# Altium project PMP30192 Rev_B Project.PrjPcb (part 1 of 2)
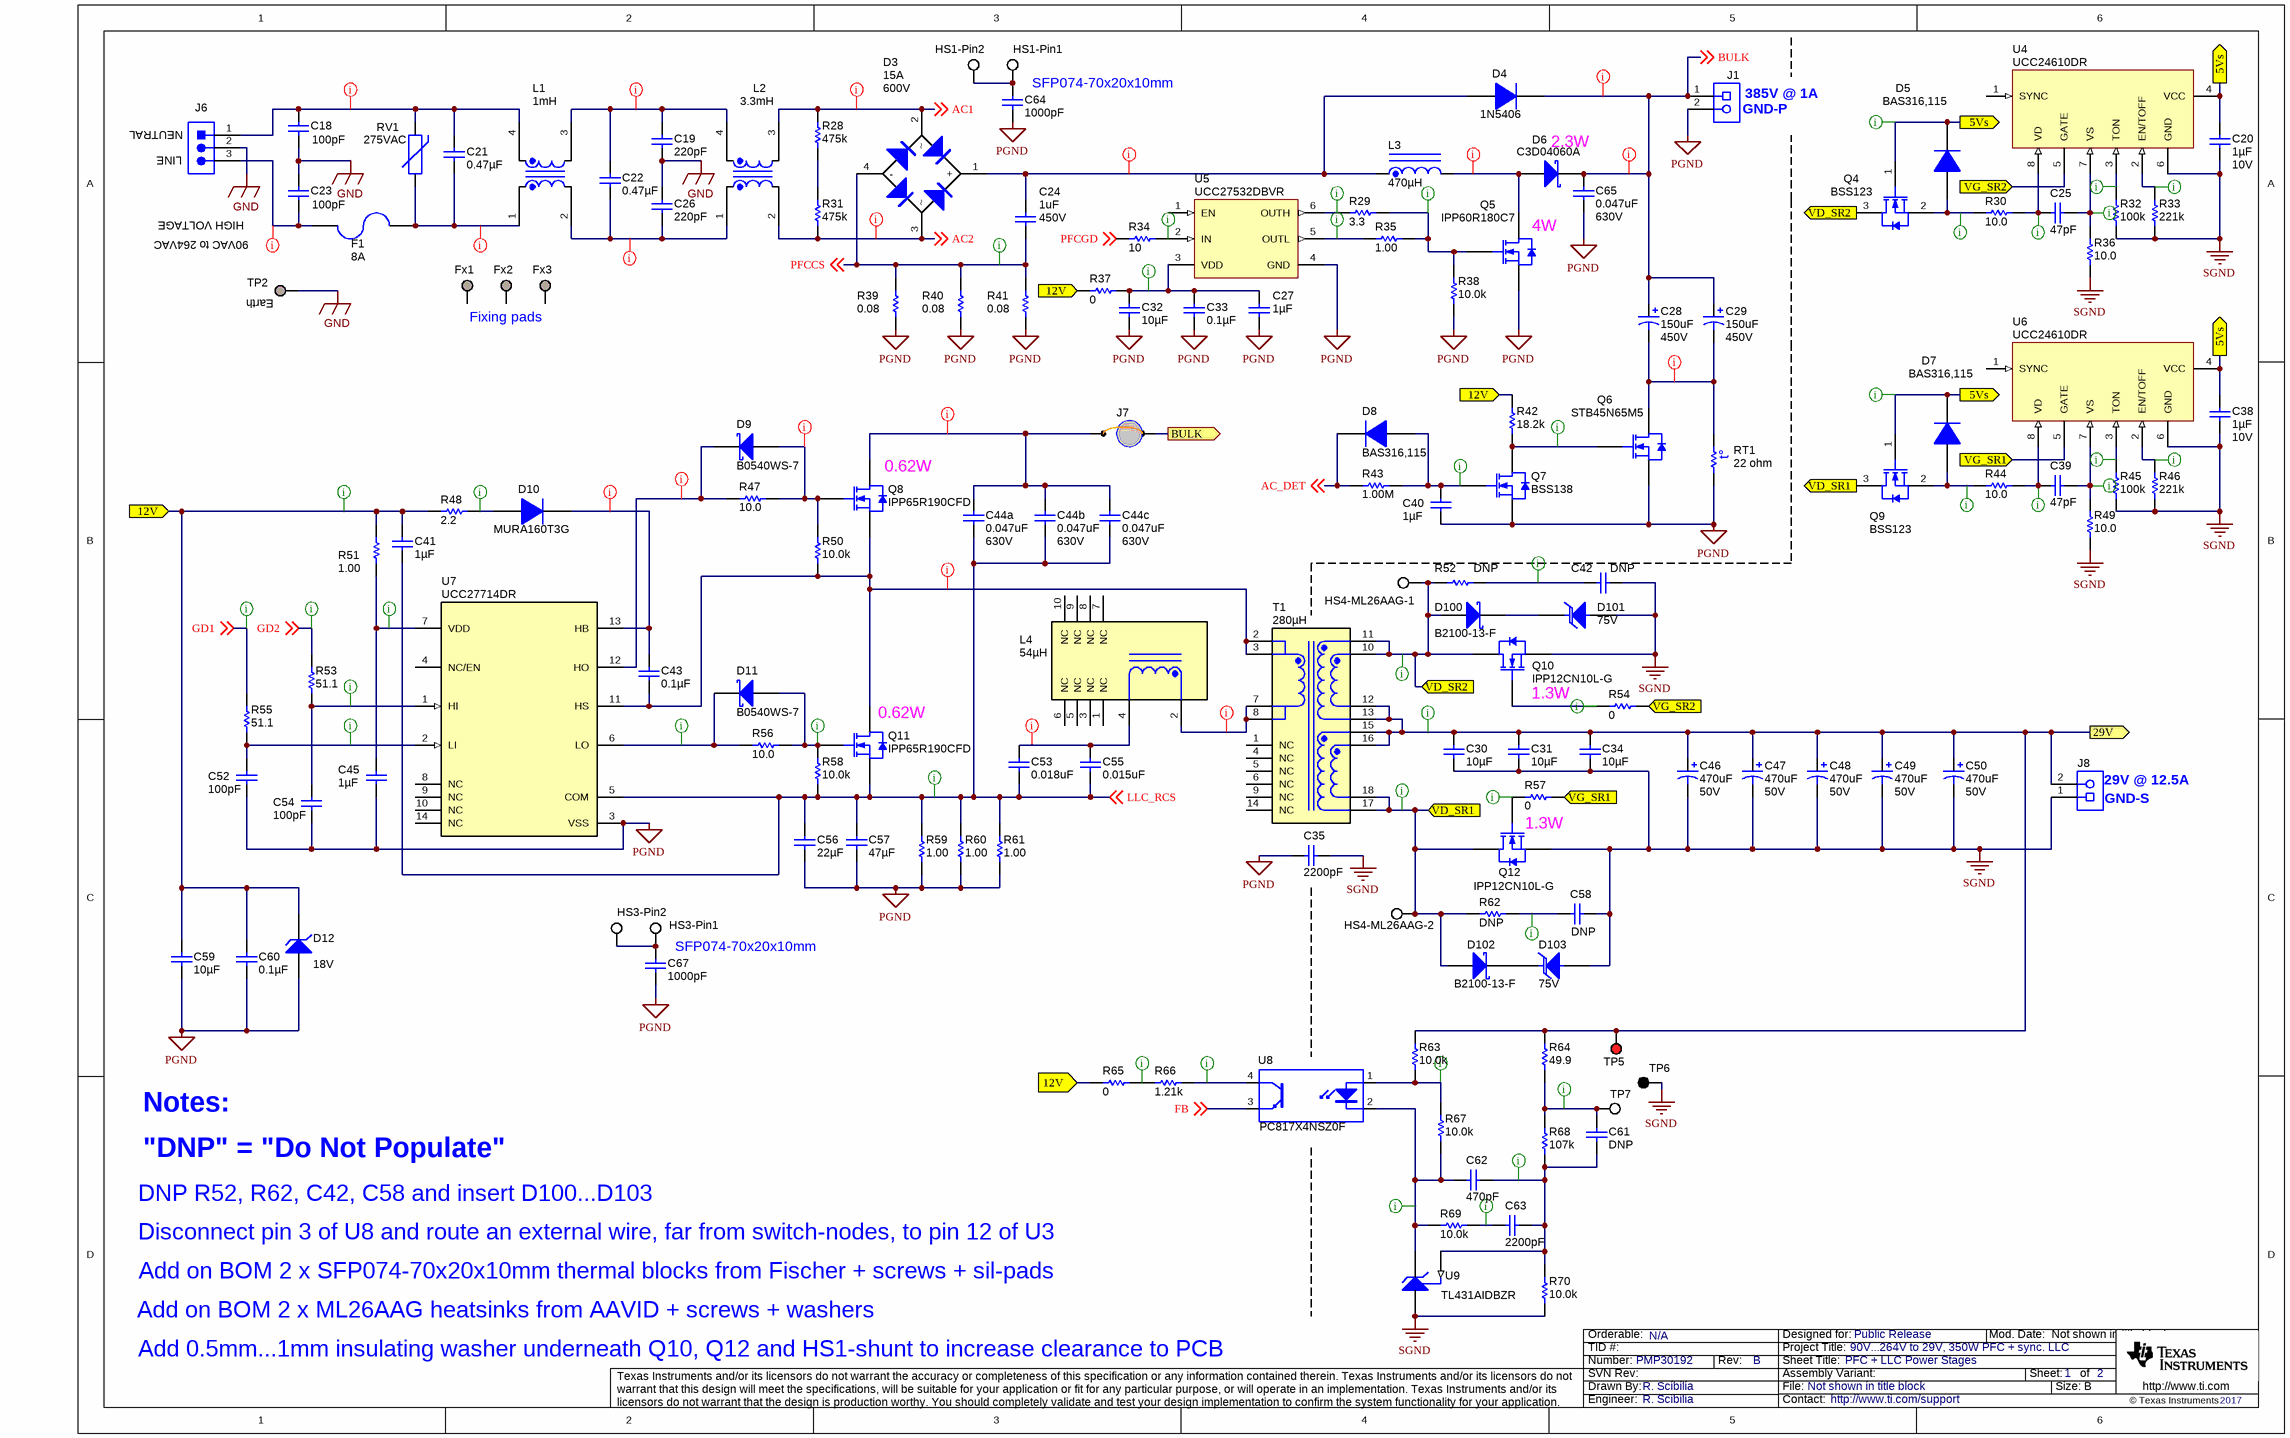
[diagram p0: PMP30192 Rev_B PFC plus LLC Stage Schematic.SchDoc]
CopyrightYear: 2017; EVM_Orderable: N/A; PCB_Layout: R. Scibilia; PCB_Rev: A; PRJ_Customer: Public Release; PRJ_Engineer: R. Scibilia; PRJ_Number: PMP30192; PRJ_Title: 90V...264V to 29V, 350W PFC + sync. LLC; SCH_Rev: B; TechSupport: http://www.ti.com/support
2 sheets, 202 parts. Net scope: flat (ports and power ports of the same name join across sheets).
Board file: PMP30192 Rev_A PCB.PcbDoc
Sheets:
  PMP30192 Rev_B PFC plus LLC Stage Schematic.SchDoc
  PMP30192 Rev_B Modulator Schematic.SchDoc

## Sheet PMP30192 Rev_B PFC plus LLC Stage Schematic.SchDoc: PFC + LLC Power Stages
size 431 x 279 mm; Date: Not shown in title block; ApprovedBy: Not shown in title block; CheckedBy: Not shown in title block; Author: Not shown in title block; CompanyName: Not shown in title block; DrawnBy: R. Scibilia; Engineer: Not shown in title block; Organization: Not shown in title block; Address1: Not shown in title block; Address2: Not shown in title block; Address3: Not shown in title block; Address4: Not shown in title block; DocumentNumber: 1; Revision: Use project parameter SCH_Rev; SheetNumber: 1; SheetTotal: 2; PageSetup: Record=PageOptions¦CenterHorizontal=True¦CenterVertical=True¦PrintScale=1.00¦XCorrection=1.00¦YCorrection=1.00¦PrintKind=0¦BorderSize=5000000¦LeftOffset=0¦BottomOffset=0¦Orientation=2¦PaperLength=1000¦PaperWidth=1000¦Scale=100¦PaperSource=15¦PrintQuality=600¦MediaType=1¦DitherType=10¦PaperKind=Letter¦PrintScaleMode=1

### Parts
C18  Value1: 100pF  [B_800x700x800]  (hidden comment: DE6B3KJ101KN3A)
C19  ValueDisplayed: 220pF  [B_800x700x800]  (hidden comment: DE6B3KJ221KN3A)
C20  ValueDisplayed: 1µF  Value2: 10V  [0603]  (hidden comment: C0603C105K8PACTU)
C21  ValueDisplayed: 0.47µF  [CAPRR2250W80L2550T850H1750]  (hidden comment: ECQ-U2A474ML)
C22  ValueDisplayed: 0.47µF  [CAPRR2250W80L2550T850H1750]  (hidden comment: ECQ-U2A474ML)
C23  Value1: 100pF  [B_800x700x800]  (hidden comment: DE6B3KJ101KN3A)
C24  value 1uF  Value2: 450V  [B32672_1800x1100x1850]  (hidden comment: B32672Z4105K000)
C25  ValueDisplayed: 47pF  [0603]  (hidden comment: C0603C470J5GACTU)
C26  ValueDisplayed: 220pF  [B_800x700x800]  (hidden comment: DE6B3KJ221KN3A)
C27  ValueDisplayed: 1µF  [0603]  (hidden comment: UMK107AB7105KA-T)
C28  value 150uF  Value2: 450V  [KXW_1800x4500]  (hidden comment: 450TXW150MEFC18X45)
C29  value 150uF  Value2: 450V  [KXW_1800x4500]  (hidden comment: 450TXW150MEFC18X45)
C30  ValueDisplayed: 10µF  [1206_180]  (hidden comment: C3216X5R1H106K160AB)
C31  ValueDisplayed: 10µF  [1206_180]  (hidden comment: C3216X5R1H106K160AB)
C32  ValueDisplayed: 10µF  [1206]  (hidden comment: GMK316AB7106KL)
C33  ValueDisplayed: 0.1µF  [0603]  (hidden comment: 06035C104KAT2A)
C34  ValueDisplayed: 10µF  [1206_180]  (hidden comment: C3216X5R1H106K160AB)
C35  ValueDisplayed: 2200pF  [E_900x700x900]  (hidden comment: DE6E3KJ222MN3A)
C38  ValueDisplayed: 1µF  Value2: 10V  [0603]  (hidden comment: C0603C105K8PACTU)
C39  ValueDisplayed: 47pF  [0603]  (hidden comment: C0603C470J5GACTU)
C40  ValueDisplayed: 1µF  [0603]  (hidden comment: UMK107AB7105KA-T)
C41  ValueDisplayed: 1µF  [0603]  (hidden comment: UMK107AB7105KA-T)
C42  value DNP  [1206]  (hidden comment: Used in BOM report)
C43  ValueDisplayed: 0.1µF  [0603]  (hidden comment: 06035C104KAT2A)
C44a  value 0.047uF  Value2: 630V  [1210_220]  (hidden comment: GRM32DR72J473KW01L)
C44b  value 0.047uF  Value2: 630V  [1210_220]  (hidden comment: GRM32DR72J473KW01L)
C44c  value 0.047uF  Value2: 630V  [1210_220]  (hidden comment: GRM32DR72J473KW01L)
C45  ValueDisplayed: 1µF  [0603]  (hidden comment: UMK107AB7105KA-T)
C46  value 470uF  Value2: 50V  [ZLH_1250x2500]  (hidden comment: 50ZLH470M12.5X20)
C47  value 470uF  Value2: 50V  [ZLH_1250x2500]  (hidden comment: 50ZLH470M12.5X20)
C48  value 470uF  Value2: 50V  [ZLH_1250x2500]  (hidden comment: 50ZLH470M12.5X20)
C49  value 470uF  Value2: 50V  [ZLH_1250x2500]  (hidden comment: 50ZLH470M12.5X20)
C50  value 470uF  Value2: 50V  [ZLH_1250x2500]  (hidden comment: 50ZLH470M12.5X20)
C52  ValueDisplayed: 100pF  [0603]  (hidden comment: 06035A101FAT2A)
C53  value 0.018uF  [CAPRR1500W80L1800T800H1550]  (hidden comment: 121MPE183J)
C54  ValueDisplayed: 100pF  [0603]  (hidden comment: 06035A101FAT2A)
C55  value 0.015uF  [CAPRR1500W80L1800T800H1550]  (hidden comment: 121MPE153J)
C56  ValueDisplayed: 22µF  [1206_180]  (hidden comment: C3216X6S1A226M160AB)
C57  ValueDisplayed: 47µF  [1206]  (hidden comment: C3216X5R1C476M160AB)
C58  value DNP  [1206]  (hidden comment: Used in BOM report)
C59  ValueDisplayed: 10µF  [1206]  (hidden comment: GMK316AB7106KL)
C60  ValueDisplayed: 0.1µF  [0603]  (hidden comment: 06035C104KAT2A)
C61  DNP  [0603]
C62  ValueDisplayed: 470pF  [0603]  (hidden comment: GCM1885C1H471JA16D)
C63  ValueDisplayed: 2200pF  [0603]  (hidden comment: C0603C222K5RACTU)
C64  ValueDisplayed: 1000pF  [1206]  (hidden comment: GRM31BR72J102KW01L)
C65  value 0.047uF  Value2: 630V  [1210_220]  (hidden comment: GRM32DR72J473KW01L)
C67  ValueDisplayed: 1000pF  [1206]  (hidden comment: GRM31BR72J102KW01L)
D3  value 600V  Value1: 15A  [GBJ]  (hidden comment: GBJL2006-BP)
D4  1N5406  [DO-201AD]
D5  BAS316,115  [sod-323]
D6  C3D04060A  [TO-220-F2]
D7  BAS316,115  [sod-323]
D8  BAS316,115  [sod-323]
D9  B0540WS-7  [SOD-323]
D10  MURA160T3G  [SMA]
D11  B0540WS-7  [SOD-323]
D12  value 18V  [SOD-123]  (hidden comment: MMSZ5248B-7-F)
D100  B2100-13-F  [SMB]
D101  value 75V  [SMB]  (hidden comment: SMBJ75A-13-F)
D102  B2100-13-F  [SMB]
D103  value 75V  [SMB]  (hidden comment: SMBJ75A-13-F)
F1  value 8A  [FUSE_0216]  (hidden comment: 0216008.MXESPP)
Fx1  TESTPOINT  [PAD_100mil-40milhole]  (value not drawn)  (no BOM)
Fx2  TESTPOINT  [PAD_100mil-40milhole]  (value not drawn)  (no BOM)
Fx3  TESTPOINT  [PAD_100mil-40milhole]  (value not drawn)  (no BOM)
HS1-Pin1  5012  [Keystone5012]  (value not drawn)
HS1-Pin2  5012  [Keystone5012]  (value not drawn)
HS3-Pin1  5012  [Keystone5012]  (value not drawn)
HS3-Pin2  5012  [Keystone5012]  (value not drawn)
HS4-ML26AAG-1  5012  [Keystone5012]  (value not drawn)
HS4-ML26AAG-2  5012  [Keystone5012]  (value not drawn)
J1  1715721  [PhoenixContact_1715721]  (value not drawn)
J6  1-1318301-3  [TE_1-1318301-3]  (value not drawn)
J7  923345-03-C  [923345-03-C]  (value not drawn)
J8  1732720  [Phoenix_1732720]  (value not drawn)
L1  value 1mH  [WE-CMBH]  (hidden comment: 744834101)
L2  value 3.3mH  [WE-CMBH]  (hidden comment: 744834433)
L3  ValueDisplayed: 470µH  [750316597]  (hidden comment: 750316597)
L4  ValueDisplayed: 54µH  [750316600]  (hidden comment: 750316600)
Q4  BSS123  [SOT-23]
Q5  IPP60R180C7  [TO-220AB]
Q6  STB45N65M5  [DDPAK]
Q7  BSS138  [SOT-23]
Q8  IPP65R190CFD  [TO-220AB]
Q9  BSS123  [SOT-23]
Q10  value IPP12CN10L-G  [TO-220AB]  (hidden comment: IPP12CN10L G)
Q11  IPP65R190CFD  [TO-220AB]
Q12  value IPP12CN10L-G  [TO-220AB]  (hidden comment: IPP12CN10L G)
R28  ValueDisplayed: 475k  [1206]  (hidden comment: ERJ-8ENF4753V)
R29  ValueDisplayed: 3.3  [0603]  (hidden comment: CRCW06033R30JNEA)
R30  ValueDisplayed: 10.0  [0603]  (hidden comment: RC0603FR-0710RL)
R31  ValueDisplayed: 475k  [1206]  (hidden comment: ERJ-8ENF4753V)
R32  value 100k  [0603]  (hidden comment: CRCW0603100KFKEA)
R33  value 221k  [0603]  (hidden comment: CRCW0603221KFKEA)
R34  ValueDisplayed: 10  [0603]  (hidden comment: CRCW060310R0JNEA)
R35  ValueDisplayed: 1.00  [0603]  (hidden comment: CRCW06031R00FKEA)
R36  ValueDisplayed: 10.0  [0603]  (hidden comment: RC0603FR-0710RL)
R37  ValueDisplayed: 0  [1206]  (hidden comment: CRCW12060000Z0EA)
R38  value 10.0k  [0603]  (hidden comment: CRCW060310K0FKEA)
R39  ValueDisplayed: 0.08  [2512]  (hidden comment: CRA2512-FZ-R080ELF)
R40  ValueDisplayed: 0.08  [2512]  (hidden comment: CRA2512-FZ-R080ELF)
R41  ValueDisplayed: 0.08  [2512]  (hidden comment: CRA2512-FZ-R080ELF)
R42  ValueDisplayed: 18.2k  [0603]  (hidden comment: RC0603FR-0718K2L)
R43  ValueDisplayed: 1.00M  [0603]  (hidden comment: RC0603FR-071ML)
R44  ValueDisplayed: 10.0  [0603]  (hidden comment: RC0603FR-0710RL)
R45  value 100k  [0603]  (hidden comment: CRCW0603100KFKEA)
R46  value 221k  [0603]  (hidden comment: CRCW0603221KFKEA)
R47  ValueDisplayed: 10.0  [1206]  (hidden comment: RC1206FR-0710RL)
R48  ValueDisplayed: 2.2  [0805_HV]  (hidden comment: CRCW08052R20JNEA)
R49  ValueDisplayed: 10.0  [0603]  (hidden comment: RC0603FR-0710RL)
R50  value 10.0k  [0603]  (hidden comment: CRCW060310K0FKEA)
R51  value 1.00  [0805_HV]  (hidden comment: ERJ-6RQF1R0V)
R52  ERJ-1TYJ100U  [2512]  (value not drawn)
R53  ValueDisplayed: 51.1  [0603]  (hidden comment: CRCW060351R1FKEA)
R54  ValueDisplayed: 0  [0603]  (hidden comment: CRCW06030000Z0EA)
R55  ValueDisplayed: 51.1  [0603]  (hidden comment: CRCW060351R1FKEA)
R56  ValueDisplayed: 10.0  [1206]  (hidden comment: RC1206FR-0710RL)
R57  ValueDisplayed: 0  [0603]  (hidden comment: CRCW06030000Z0EA)
R58  value 10.0k  [0603]  (hidden comment: CRCW060310K0FKEA)
R59  ValueDisplayed: 1.00  [2512]  (hidden comment: ERJ-1TRQF1R0U)
R60  ValueDisplayed: 1.00  [2512]  (hidden comment: ERJ-1TRQF1R0U)
R61  ValueDisplayed: 1.00  [2512]  (hidden comment: ERJ-1TRQF1R0U)
R62  ERJ-1TYJ100U  [2512]  (value not drawn)
R63  value 10.0k  [0603]  (hidden comment: CRCW060310K0FKEA)
R64  ValueDisplayed: 49.9  [0603]  (hidden comment: RC0603FR-0749R9L)
R65  ValueDisplayed: 0  [0603]  (hidden comment: CRCW06030000Z0EA)
R66  ValueDisplayed: 1.21k  [0603]  (hidden comment: RC0603FR-071K21L)
R67  value 10.0k  [0603]  (hidden comment: CRCW060310K0FKEA)
R68  ValueDisplayed: 107k  [0603]  (hidden comment: RC0603FR-07107KL)
R69  value 10.0k  [0603]  (hidden comment: CRCW060310K0FKEA)
R70  value 10.0k  [0603]  (hidden comment: CRCW060310K0FKEA)
RT1  value 22 ohm  [S237]  (hidden comment: B57237S220M)
RV1  value 275VAC  [VAR_B72214S0271]  (hidden comment: B72214S0271K101)
T1  ValueDisplayed: 280µH  [Wurth_750316599]  (hidden comment: 750316599)
TP2  TESTPOINT  [PAD_100mil-40milhole]  (value not drawn)  (no BOM)
TP5  5010  [Keystone5010]  (value not drawn)
TP6  5011  [Keystone5011]  (value not drawn)
TP7  5012  [Keystone5012]  (value not drawn)
U4  UCC24610DR  [D0008A_N]
U5  UCC27532DBVR  [DBV0006A_N]
U6  UCC24610DR  [D0008A_N]
U7  UCC27714DR  [D0014A_N]
U8  PC817X4NSZ0F  [DIP762W60P254L460H350Q4B]
U9  TL431AIDBZR  [DBZ0003A_N]

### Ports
5Vs, 12V, 29V, BULK, VD_SR1, VD_SR2, VG_SR1, VG_SR2

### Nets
GND: C18.2 C19.2 C23.1 C26.1 J6.2 TP2.1
PGND: C27.1 C32.1 C33.2 C35.2 C40.1 C45.1 C52.2 C54.1 C56.2 C57.2 C59.1 C60.2 C64.2 C65.1 C67.2 D12.2(A) J1.2 Q5.3(S) Q6.3(S) Q7.2(S) R38.2 R39.1 R40.1 R41.1 R59.1 R60.1 R61.1 RT1.1 U5.4(GND) U7.3(VSS)
SGND: C20.2 C30.2 C31.2 C34.2 C35.1 C38.2 C42.1 C46.2(-) C47.2(-) C48.2(-) C49.2(-) C50.2(-) C58.1 D101.2(A) D103.2(A) J8.1 Q10.3(S) Q12.3(S) R32.1 R33.1 R36.2 R45.1 R46.1 R49.2 R70.1 TP6.1 U4.6(GND) U6.6(GND) U9.3(ANODE)
5Vs: C20.1 C38.1 D5.1(K) D7.1(K) Q4.1(G) Q9.1(G) U4.4(VCC) U6.4(VCC) ; port 5Vs
12V: C41.2 C59.2 C60.1 D12.1(K) R37.1 R42.2 R48.1 R51.2 R65.1 ; port 12V
29V: C30.1 C31.1 C34.1 C46.1(+) C47.1(+) C48.1(+) C49.1(+) C50.1(+) J8.2 R63.2 R64.2 T1.12 T1.13 T1.15 T1.16 TP5.1 ; port 29V
AC1: D3.2 L2.3 R28.2 ; off-sheet AC1
AC2: D3.3 L2.2 R31.1 ; off-sheet AC2
AC_DET: D8.1(K) R43.1 ; off-sheet AC_DET
BULK: C28.1(+) C29.1(+) C65.2 D4.1(K) D6.1(K) J1.1 ; off-sheet BULK
BULK: J7.2 ; port BULK  [a separate net that carries the same name]
FB: U8.3(E) ; off-sheet FB
GD1: R55.2 ; off-sheet GD1
GD2: R53.2 ; off-sheet GD2
LLC_RCS: C41.1 C44a.1 C44b.1 C44c.1 C53.2 C55.2 C56.1 C57.1 Q11.3(S) R58.2 R59.2 R60.2 R61.2 U7.5(COM) ; off-sheet LLC_RCS
PFCCS: C24.2 D3.4(-) R39.2 R40.2 R41.2 ; off-sheet PFCCS
PFCGD: R34.2 ; off-sheet PFCGD
VD_SR1: D102.2(A) HS4-ML26AAG-2.1 Q9.3(D) Q12.2(D) R62.1 T1.17 T1.18 ; port VD_SR1
VD_SR2: D100.2(A) HS4-ML26AAG-1.1 Q4.3(D) Q10.2(D) R52.1 T1.10 T1.11 ; port VD_SR2
VG_SR1: R57.2 U6.5(GATE) ; port VG_SR1
VG_SR2: R54.2 U4.5(GATE) ; port VG_SR2
NetC18_1: C18.1 C21.1 J6.1 L1.4 RV1.2
NetC19_1: C19.1 C22.1 L1.3 L2.4
NetC21_2: C21.2 F1.1 L1.1 RV1.1
NetC22_2: C22.2 C26.2 L1.2 L2.1
NetC23_2: C23.2 F1.2 J6.3
NetC24_1: C24.1 D3.1(+) D4.2(A) L3.1
NetC25_1: C25.1 R36.1 U4.7(VS)
NetC25_2: C25.2 R30.2 U4.8(VD)
NetC27_2: C27.2 C32.2 C33.1 R37.2 U5.3(VDD)
NetC28_2: C28.2(-) C29.2(-) Q6.4(D) RT1.2
NetC39_1: C39.1 R49.1 U6.7(VS)
NetC39_2: C39.2 R44.2 U6.8(VD)
NetC40_2: C40.2 D8.2(A) Q7.1(G) R43.2
NetC42_2: C42.2 R52.2
NetC43_1: C43.1 D10.1(K) U7.13(HB)
NetC43_2: C43.2 Q8.3(S) Q11.2(D) R50.1 T1.2 T1.3 U7.11(HS)
NetC44a_2: C44a.2 C44b.2 C44c.2 J7.1 Q8.2(D)
NetC45_2: C45.2 R51.1 U7.7(VDD)
NetC52_1: C52.1 R55.1 U7.2(LI)
NetC53_1: C53.1 C55.1 L4.4
NetC54_2: C54.2 R53.1 U7.1(HI)
NetC58_2: C58.2 R62.2
NetC61_1: C61.1 R64.1 R68.2 TP7.1
NetC61_2: C61.2 C62.2 C63.2 R68.1 R70.2 U9.2(REF)
NetC62_1: C62.1 R67.1 R69.1 U8.2(K) U9.1(CATHODE)
NetC63_1: C63.1 R69.2
NetC64_1: C64.1 HS1-Pin1.1 HS1-Pin2.1
NetC67_1: C67.1 HS3-Pin1.1 HS3-Pin2.1
NetD5_2: D5.2(A) Q4.2(S) R30.1
NetD6_2: D6.2(A) L3.2 Q5.2(D)
NetD7_2: D7.2(A) Q9.2(S) R44.1
NetD9_1: D9.1(K) R47.1 U7.12(HO)
NetD9_2: D9.2(A) Q8.1(G) R47.2 R50.2
NetD10_2: D10.2(A) R48.2
NetD11_1: D11.1(K) R56.1 U7.6(LO)
NetD11_2: D11.2(A) Q11.1(G) R56.2 R58.1
NetD100_1: D100.1(K) D101.1(K)
NetD102_1: D102.1(K) D103.1(K)
NetL4_2: L4.2 T1.7 T1.8
NetQ5_1: Q5.1(G) R29.2 R35.2 R38.1
NetQ6_1: Q6.1(G) Q7.3(D) R42.1
NetQ10_1: Q10.1(G) R54.1
NetQ12_1: Q12.1(G) R57.1
NetR28_1: R28.1 R31.2
NetR29_1: R29.1 U5.6(OUTH)
NetR32_2: R32.2 U4.3(TON)
NetR33_2: R33.2 U4.2(EN/TOFF)
NetR34_1: R34.1 U5.2(IN)
NetR35_1: R35.1 U5.5(OUTL)
NetR45_2: R45.2 U6.3(TON)
NetR46_2: R46.2 U6.2(EN/TOFF)
NetR63_1: R63.1 R67.2 U8.1(A)
NetR65_2: R65.2 R66.1
NetR66_2: R66.2 U8.4(C)

Not connected (* = marked no-connect by the designer): Fx1 1; Fx2 1; Fx3 1; L4 1(NC) 3(NC) 5(NC) 6(NC) 7(NC) 8(NC) 9(NC) 10(NC); T1 1(NC) 4(NC) 5(NC) 6(NC) 9(NC) 14(NC); U4 1(SYNC); U5 1(EN); U6 1(SYNC); U7 4(NC/EN) 8(NC) 9(NC) 10(NC) 14(NC)

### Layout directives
rule Clearance Constraint [Clearance = 40mil]: AC1, AC2, BULK, NetC18_1, NetC19_1, NetC21_2, NetC22_2, NetC23_2, NetC24_1, NetC28_2, NetC43_1, NetC43_2, NetC44a_2, NetC53_1, NetD6_2, NetD9_1, NetD9_2, NetL4_2
rule Clearance Constraint [Clearance = 10mil]: 5Vs, 12V, 29V, GD1, GD2, LLC_RCS, NetC25_1, NetC25_2, NetC27_2, NetC39_1, NetC39_2, NetC40_2, NetC42_2, NetC45_2, NetC52_1, NetC54_2, NetC58_2, NetC61_1, NetC61_2, NetC62_1, NetC63_1, NetD5_2, NetD7_2, NetD10_2, NetD11_1, NetD11_2, NetQ5_1, NetQ6_1, NetQ10_1, NetQ12_1, NetR29_1, NetR32_2, NetR33_2, NetR34_1, NetR35_1, NetR45_2, NetR46_2, NetR63_1, NetR65_2, NetR66_2, PFCCS, VD_SR1, VD_SR2

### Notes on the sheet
- SFP074-70x20x10mm
- (near J1) 385V @ 1A
- (near J6) NEUTRAL
- (near J6) LINE
- 2.3W
- (near J1) GND-P
- HIGH VOLTAGE
- (near Q5) 4W
- 90VAC to 264VAC
- (near TP2) Earth
- Fixing pads
- (near Q8) 0.62W
- (near Q11) 0.62W
- (near Q10) 1.3W
- (near J8) GND-S
- (near J8) 29V @ 12.5A
- (near Q12) 1.3W
- Notes:
- "DNP" = "Do Not Populate"
- DNP R52, R62, C42, C58 and insert D100...D103
- Disconnect pin 3 of U8 and route an external wire, far from switch-nodes, to pin 12 of U3
- Add on BOM 2 x ML26AAG heatsinks from AAVID + screws + washers
- Add on BOM 2 x SFP074-70x20x10mm thermal blocks from Fischer + screws + sil-pads
- Add 0.5mm...1mm insulating washer underneath Q10, Q12 and HS1-shunt to increase clearance to PCB

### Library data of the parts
C18 C23 = DE6B3KJ221KN3A: CAP CER 100PF 300VAC 10% RADIAL; Manufacturer: MuRata; Polarized: N; CompType: Capacitor; U/M: EA; Cap_F: 0.00000000022; Tolerance_%: 10; VDC_V: 300; TempCo: B; TaMin_C: -40; TaMax_C: 125; Cap_Case: 8x7x8mm
C19 C26 = DE6B3KJ221KN3A: CAP, CERM, 220 pF, 300 V, +/- 10%, B, TH, 2- Leads, Body 8x7mm, Pin Spacing 7.5mm; Manufacturer: MuRata; Polarized: N; CompType: Capacitor; Value: 220pF; U/M: EA; Cap_F: 0.00000000022; Tolerance_%: 10; Value1: Unknown; VDC_V: 300; Value2: 300V; TaMin_C: -40; TaMax_C: 125; Cap_Case: 8x7x8mm
C20 C38 = C0603C105K8PACTU: CAP, CERM, 1 µF, 10 V, +/- 10%, X5R, 0603; Manufacturer: Kemet; Polarized: N; CompType: Capacitor; Value: 1uF; U/M: EA; Cap_F: 0.000001; Tolerance_%: 10; Value1: Unknown; TaMin_C: -55; TaMax_C: 85
C21 C22 = ECQ-U2A474ML: CAP, Film, 0.47uF, 275V, +/-20%, TH; Manufacturer: Panasonic; Polarized: N; CompType: Capacitor; U/M: EA; Cap_F: 0.00000047; Tolerance_%: 20; Value1: Unknown; VDC_V: 275; TaMin_C: -40; TaMax_C: 100; Cap_Case: Radial 25x8.5x18.5
C24 = B32672Z5684K000: CAP, Film, 1 µF, 277 450 VDC,+/- 10%, TH; Manufacturer: TDK; Polarized: N; CompType: Capacitor; ValueDisplayed: 1µF; U/M: EA; Cap_F: 0.00000068; Tolerance_%: 10; VDC_V: 450; TaMin_C: -55; TaMax_C: -125; Cap_Case: 18x11x18.5mm; SizeAreaWB_mm2: 260; SizeArea_mm2: 198; SizeX_mm: 18; SizeY_mm: 11; SizeZ_mm: 18.5; AEC Category: Q200; Green_Lifecycle: Not Set; Green_REACh: Incomplete; VAC: 277
C25 C39 = C0603C470J5GACTU: CAP, CERM, 47 pF, 50 V, +/- 5%, C0G/NP0, 0603; Manufacturer: Kemet; Polarized: N; CompType: Capacitor; Value: 47pF; U/M: EA; Cap_F: 0.000000000047; Tolerance_%: 5; Value1: Unknown; VDC_V: 50; Value2: 50V; TaMin_C: -55; TaMax_C: 125; SizeArea_mm2: 1.28; SizeAreaWB_mm2: 4.68; SizeX_mm: 1.6; SizeY_mm: 0.8; SizeZ_mm: 1; AEC Category: Q200
C27 C40 C41 C45 = UMK107AB7105KA-T: CAP, CERM, 1 µF, 50 V, +/- 10%, X7R, 0603; Manufacturer: Taiyo Yuden; Polarized: N; CompType: Capacitor; Value: 1uF; U/M: EA; Cap_F: 0.000001; Tolerance_%: 10; Value1: Unknown; VDC_V: 50; Value2: 50V; TaMin_C: -55; TaMax_C: 125
C28 C29 = 400KXW220MEFC18X45: CAP, AL, 150 µF, 450 V, +/- 20%, TH; Manufacturer: United-Chemicon; Polarized: Y; CompType: Capacitor; ValueDisplayed: 150µF; U/M: EA; Cap_F: 0.00015; Tolerance_%: 20; Value1: Unknown; VDC_V: 450; IRMS_A: 1.4; TaMin_C: -25; TaMax_C: 105; Cap_Case: 18x45mm; SizeAreaWB_mm2: 400; SizeArea_mm2: 324; SizeX_mm: 18; SizeZ_mm: 45; AEC Qualified: N
C30 C31 C34 = C3216X5R1H106K160AB: CAP, CERM, 10 µF, 50 V, +/- 10%, X5R, 1206; Manufacturer: TDK; Polarized: N; CompType: Capacitor; Value: 10uF; U/M: EA; Cap_F: 0.00001; Tolerance_%: 10; ESR_ohm: 0.002229; Value1: 0.002229 ohm; VDC_V: 50; Value2: 50V; IRMS_A: 4.85932; TaMin_C: -55; TaMax_C: 85; SizeArea_mm2: 5.12; SizeAreaWB_mm2: 10.92; SizeX_mm: 3.2; SizeY_mm: 1.6; SizeZ_mm: 1.8; AEC Category: Q200
C32 C59 = GMK316AB7106KL: CAP, CERM, 10uF, 35V, +/-10%, X7R, 1206; Manufacturer: Taiyo Yuden; Polarized: N; CompType: Capacitor; U/M: EA; Cap_F: 0.00001; Tolerance_%: 10; Value1: Unknown; VDC_V: 35; TaMin_C: -55; TaMax_C: 125
C33 C43 C60 = 06035C104KAT2A: CAP, CERM, 0.1uF, 50V, +/-10%, X7R, 0603; Manufacturer: AVX; Polarized: N; CompType: Capacitor; U/M: EA; Cap_F: 0.0000001; Tolerance_%: 10; Value1: Unknown; VDC_V: 50; TaMin_C: -55; TaMax_C: 125
C35 = DE6E3KJ222MN3A: CAP, CERM, 2200 pF, 300 V, +/- 20%, E, TH, 2- Leads, Body 9x7mm, Pin Spacing 7.5mm; Manufacturer: MuRata; Polarized: N; CompType: Capacitor; Value: 2200pF; U/M: EA; Cap_F: 0.0000000022; Tolerance_%: 20; Value1: Unknown; VDC_V: 300; Value2: 300V; TaMin_C: -40; TaMax_C: 125; Cap_Case: 9x7x9mm; SizeArea_mm2: 63; SizeAreaWB_mm2: 99; SizeX_mm: 9; SizeY_mm: 7; SizeZ_mm: 12; AEC Category: Q200
C42 C58 = Capacitor: CAP, CERM, xxxF, xxV, [TempCo], xx%, [PackageReference]; Polarized: N; U/M: EA
C44a C44b C44c C65 = GRM32DR72J473KW01L: CAP, CERM, 0.047 µF, 630 V, +/- 10%, X7R, 1210; Manufacturer: MuRata; Polarized: N; CompType: Capacitor; U/M: EA; Cap_F: 0.000000047; Tolerance_%: 10; Value1: Unknown; VDC_V: 630; TaMin_C: -55; TaMax_C: 125; Cap_Case: 1210; SizeArea_mm2: 8; SizeAreaWB_mm2: 14.7; SizeX_mm: 3.2; SizeY_mm: 2.5; SizeZ_mm: 2.2; AEC Category: Q200
C46-C50 = 63ZLH470M12.5X25: CAP, AL, 470 µF, 50 V, +/- 20%, 0.027 ohm, TH; Manufacturer: Rubycon; Polarized: Y; CompType: Capacitor; ValueDisplayed: 470µF; U/M: EA; Cap_F: 0.00047; Tolerance_%: 20; VDC_V: 50; ESR_ohm: 0.027; IRMS_A: 2.05; TaMin_C: -40; TaMax_C: 105; SizeAreaWB_mm2: 210.25; SizeArea_mm2: 156.25; SizeX_mm: 12.5; AEC Category: Q200
C52 C54 = 06035A101FAT2A: CAP, CERM, 100pF, 50V, +/-1%, C0G/NP0, 0603; Manufacturer: AVX; CompType: Capacitor; Tolerance_%: 1; Value1: Unknown; VDC_V: 50; U/M: EA; Polarized: N; Cap_F: 0.0000000001; TaMin_C: -55; TaMax_C: 125
C53 = 121MPE223J: CAP, Film, 0.018 µF, 1250 V, +/- 5%, TH; Manufacturer: Rubycon; Polarized: N; CompType: Capacitor; U/M: EA; Cap_F: 0.000000022; Tolerance_%: 5; Value1: Unknown; VDC_V: 1250; Value2: 1250V; TaMin_C: -40; TaMax_C: 105; Cap_Case: 18x8x15.5mm; AEC Category: Q200
C55 = 121MPE223J: CAP, Film, 0.015 µF, 1250 V, +/- 5%, TH; Manufacturer: Rubycon; Polarized: N; CompType: Capacitor; U/M: EA; Cap_F: 0.000000022; Tolerance_%: 5; Value1: Unknown; VDC_V: 1250; Value2: 1250V; TaMin_C: -40; TaMax_C: 105; Cap_Case: 18x8x15.5mm; AEC Category: Q200
C56 = C3216X6S1A226M160AB: CAP, CERM, 22 µF, 10 V, +/- 20%, X6S, 1206; Manufacturer: TDK; Polarized: N; CompType: Capacitor; Value: 22uF; U/M: EA; Cap_F: 0.000022; Tolerance_%: 20; ESR_ohm: 0.002398; Value1: 0.002398 ohm; VDC_V: 10; Value2: 10V; IRMS_A: 4.68507; TaMin_C: -55; TaMax_C: 105; SizeArea_mm2: 5.12; SizeAreaWB_mm2: 10.92; SizeX_mm: 3.2; SizeY_mm: 1.6; SizeZ_mm: 1.8; AEC Category: Q200
C57 = C3216X5R1C476M160AB: CAP, CERM, 47 µF, 16 V, +/- 15%, X5R, 1206; Manufacturer: TDK; Polarized: N; CompType: Capacitor; Value: 47uF; U/M: EA; Cap_F: 0.000047; Tolerance_%: 15; Value1: Unknown; VDC_V: 16; Value2: 16V; TaMin_C: -55; TaMax_C: 85; SizeArea_mm2: 5.12; SizeAreaWB_mm2: 10.92; SizeX_mm: 3.2; SizeY_mm: 1.6; SizeZ_mm: 1.35; AEC Category: Q200
C61 = GRM1885C1H221JA01D: Manufacturer: MuRata; Polarized: N; CompType: Capacitor; U/M: EA; Cap_F: 0.00000000022; Tolerance_%: 5; Value1: Unknown; VDC_V: 50; Value2: 50V; TempCo: C0G/NP0; TaMin_C: -55; TaMax_C: 125; SizeArea_mm2: 1.28; SizeAreaWB_mm2: 4.68; SizeX_mm: 1.6; SizeY_mm: 0.8; SizeZ_mm: 1; AEC Category: Q200
C62 = GCM1885C1H471JA16D: CAP, CERM, 470 pF, 50 V,+/- 5%, C0G/NP0, AEC-Q200 Grade 1, 0603; Manufacturer: MuRata; Polarized: N; CompType: Capacitor; Value: 470pF; U/M: EA; Cap_F: 0.00000000047; Tolerance_%: 5; VDC_V: 50; Value2: 50V; TaMin_C: -55; TaMax_C: 125; SizeArea_mm2: 1.28; SizeAreaWB_mm2: 4.68; SizeX_mm: 1.6; SizeY_mm: 0.8; SizeZ_mm: 1; AEC Category: Q200; AEC Qualified: Y; Green_Lifecycle: Active; Green_REACh: Passed
C63 = C0603C222K5RACTU: CAP, CERM, 2200 pF, 50 V, +/- 10%, X7R, 0603; Manufacturer: Kemet; Polarized: N; CompType: Capacitor; Value: 2200pF; U/M: EA; Cap_F: 0.0000000022; Tolerance_%: 10; Value1: Unknown; VDC_V: 50; Value2: 50V; TaMin_C: -55; TaMax_C: 125; AEC Category: Q200
C64 C67 = GRM31BR72J102KW01L: CAP, CERM, 1000 pF, 630 V, +/- 10%, X7R, 1206; Manufacturer: MuRata; Polarized: N; CompType: Capacitor; Value: 1000pF; U/M: EA; Cap_F: 0.000000001; Tolerance_%: 10; Value1: Unknown; VDC_V: 630; Value2: 630V; TaMin_C: -55; TaMax_C: 125; SizeArea_mm2: 5.12; SizeAreaWB_mm2: 10.92; SizeX_mm: 3.2; SizeY_mm: 1.6; SizeZ_mm: 1.35; AEC Category: Q200
D3 = GBJ3502-BP: Diode, P-N-Bridge, 600 V, 15 A, TH; Manufacturer: Micro Commercial Components; U/M: EA; Vf_V: 1.05; Value2: 1.05V; Io_A: 15; Vr_V: 600; TJmax_C: 150; RJC_CperW: 0.6; SizeAreaWB_mm2: 211.2; SizeArea_mm2: 138; SizeX_mm: 30; SizeY_mm: 4.6; SizeZ_mm: 24; AEC Category: Q101
D4 = 1N5406: Diode, Switching-Bridge, 600V, 3A, TH; Manufacturer: Vishay-Semiconductor; U/M: EA; Vf_V: 1.2; Value2: 1.2V; Io_A: 3; Vr_V: 600; TJmax_C: 150
D5 D7 D8 = BAS316,115: Diode, Ultrafast, 100 V, 0.25 A, SOD-323; Manufacturer: NXP Semiconductor; U/M: EA; Vf_V: 1.4; Value1: 0.25A; Value2: 1.4V; Io_A: 0.25; Vr_V: 100; TJmax_C: 150
D6 = C3D04060A: Diode, Schottky, 600V, 4A, TH; Manufacturer: Cree; U/M: EA; Vf_V: 1.8; Value2: 1.8V; Io_A: 4; Vr_V: 600; TJmax_C: 175; RJC_CperW: 11.5
D9 D11 = B0540WS-7: Diode, Schottky, 40 V, 0.5 A, SOD-323; Manufacturer: Diodes Inc.; U/M: EA; Vf_V: 0.55; Value1: 0.5A; Value2: 0.55V; Io_A: 0.5; Vr_V: 40; TJmax_C: 125; SizeAreaWB_mm2: 8.695; SizeArea_mm2: 3.645; SizeX_mm: 2.7; SizeY_mm: 1.35; SizeZ_mm: 1; AEC Category: Q101; Green_Lifecycle: Active; Green_REACh: Passed
D10 = MURA160T3G: Diode, Ultrafast, 600 V, 1 A, SMA; Manufacturer: ON Semiconductor; U/M: EA; Vf_V: 1.05; Value1: 1A; Value2: 1.05V; Io_A: 1; Vr_V: 600; TJmax_C: 175; AEC Category: Q101
D12 = MMSZ5248B-7-F: Diode, Zener, 18V, 500mW, SOD-123; Manufacturer: Diodes Inc.; SymbolCreator: a0412235; U/M: EA; Power_W: 0.5; Vz_V: 18; Value1: 0.5W; RJA_CperW: 350
D100 D102 = B2100-13-F: Diode, Schottky, 100 V, 2 A, SMB; Manufacturer: Diodes Inc.; U/M: EA; Vf_V: 0.79; Value1: 2A; Value2: 0.79V; Io_A: 2; Vr_V: 100; TJmax_C: 150; RJC_CperW: 15; SizeAreaWB_mm2: 44.156; SizeArea_mm2: 21.336; SizeX_mm: 5.6; SizeY_mm: 3.81; SizeZ_mm: 2.6; AEC Category: Q101; Green_Lifecycle: Active; Green_REACh: Passed
D101 D103 = SMBJ75A-13-F: Diode, TVS, Uni, 75 V, 121 Vc, SMB; Manufacturer: Diodes Inc.; U/M: EA; Power_W: 5; Vr_V: 75; Value1: 5W; SizeAreaWB_mm2: 44.156; SizeArea_mm2: 21.336; SizeX_mm: 5.6; SizeY_mm: 3.81; SizeZ_mm: 2.6; AEC Category: Q101
F1 = 0216008.MXESPP: Fuse, 8A, 250V, TH; Manufacturer: Littelfuse; U/M: EA; OpeningTime_200%_max: 30; VDC_V: 250; Rtyp_Ohm: 0.0123; Soldering_Wave_MaxTemp_C: 260; Soldering_Wave_MaxTime_s: 5
Fx1-Fx3 TP2 = PAD_100mil-40milhole: 100mil pad, 40mil hole; Manufacturer: Any
HS1-Pin1 HS1-Pin2 HS3-Pin1 HS3-Pin2 HS4-ML26AAG-1 HS4-ML26AAG-2 TP7 = 5012: Test Point, Multipurpose, White, TH; Manufacturer: Keystone; CompType: Test Point Loop; U/M: EA
J1 = 1715721: Terminal Block, 5.08 mm, 2x1, TH; Manufacturer: Phoenix Contact; SymbolCreator: a0412235; Pitch_mm: 5.08; Gender: Female; Row_Count: 1; ContactFinish: Tin; Current_A: 17.5; Voltage_V: 400; Cert_CSA: Y; Cert_CULUS: N
J6 = 1-1318301-3: Header, 312mil, 3x1, Tin, TH; Manufacturer: TE Connectivity; SymbolCreator: a0799628; U/M: EA
J7 = 923345-03-C: Jumper Wire, 300mil spacing, Orange, pkg of 200; Manufacturer: 3M; SymbolCreator: a0412235
J8 = 1732720: Terminal Block, 2x1, 7.62mm, TH; Manufacturer: Phoenix Contact; SymbolCreator: a0412235
L1 = 744834405: Coupled inductor, 1 mH, 10 A, 12.5mohm, TH; Manufacturer: Wurth Elektronik; SymbolCreator: a0412235; Ind_H: 1E-3; DCR_ohm: 12.5m
L2 = 744834405: Coupled inductor, 3.3 mH, 5 A, 2 x 37mOhm, TH; Manufacturer: Wurth Elektronik; SymbolCreator: a0412235; Ind_H: 3.30E-3; DCR_ohm: 37m
L3 = 750316597: Inductor, Toroid, 470 µH, 0.11 ohm, TH; Manufacturer: Wurth Elektronik; Value: 470uH; SymbolCreator: a0412235; Ind_H: 470.0E-6; DCR_ohm: 0.11; Value2: A; SizeAreaWB_mm2: 2209; SizeArea_mm2: 2025; SizeX_mm: 45; SizeZ_mm: 20; AEC Category: Q200; AEC Qualified: N
L4 = 750316600: Inductor, 54 µH, 0.0372 ohm, TH; Manufacturer: Wurth Elektronik; SymbolCreator: Altium; Ind_H: 54.0E-6; Value: 54uH; DCR_ohm: 0.0372; Value2: A; SizeAreaWB_mm2: 803.9068; SizeArea_mm2: 694.4868; SizeX_mm: 26.67; SizeY_mm: 26.04; SizeZ_mm: 13.59; AEC Category: Q200; AEC Qualified: N
Q4 Q9 = BSS123: MOSFET, N-CH, 100 V, 0.17 A, SOT-23; Manufacturer: Fairchild Semiconductor; Alternate Manufacturer: None; U/M: EA; ChType: N; VdsMax_V: 100; Value1: 10 ohm; Rdson45_ohm: 10; Value2: 1.8 nC; QgTyp_nC: 1.8; Vgs_V: 20; IdsMax_A: 0.17
Q5 = IPP60R199CP: MOSFET, N-CH, 600 V, 45 A, TO-220AB; Manufacturer: Infineon Technologies; Alternate Manufacturer: None; U/M: EA; ChType: N; VdsMax_V: 600; Value1: 0.18 ohm; Rdson45_ohm: 0.18; Value2: 24 nC; QgTyp_nC: 24; Vgs_V: 3.5; IdsMax_A: 45; SizeAreaWB_mm2: 397.048; SizeArea_mm2: 312.208; SizeX_mm: 30.02; SizeY_mm: 10.4; SizeZ_mm: 4.82; AEC Category: Q101
Q6 = STB23NM50N: MOSFET N CH 650V 35A D2PAK; Manufacturer: ST Microelectronics; Alternate Manufacturer: None; U/M: EA; VdsMax_V: 650; Value1: ? ohm; Value2: 45 nC; QgTyp_nC: 45; Vgs_V: 25; IdsMax_A: 17
Q7 = BSS138: MOSFET, N-CH, 50 V, 0.22 A, SOT-23; Manufacturer: Fairchild Semiconductor; Alternate Manufacturer: None; U/M: EA; ChType: N; Value: 50V; VdsMax_V: 50; Value1: 6 ohm; Rdson45_ohm: 6; Value2: 1.7 nC; QgTyp_nC: 1.7; Vgs_V: 20; IdsMax_A: 0.22; SizeAreaWB_mm2: 14; SizeArea_mm2: 7.5; SizeX_mm: 2.5; SizeY_mm: 3; SizeZ_mm: 1.1; AEC Category: Q101
Q8 Q11 = IPP65R190CFD: MOSFET, N-CH, 650 V, 17.5 A, TO-220AB; Manufacturer: Infineon Technologies; Alternate Manufacturer: None; U/M: EA; ChType: N; Value: 650V; VdsMax_V: 650; Value1: 0.19 ohm; Rdson45_ohm: 0.19; Value2: 68 nC; QgTyp_nC: 68; Vgs_V: 20; IdsMax_A: 17.5; SizeAreaWB_mm2: 79.3; SizeArea_mm2: 45.9; SizeX_mm: 10.2; SizeY_mm: 4.5; SizeZ_mm: 19.4; AEC Category: Q101; Green_Lifecycle: Not Set; Green_REACh: Incomplete
Q10 Q12 = IPP023NE7N3 G: MOSFET, N-CH, 100 V, 69 A, TO-220AB; Manufacturer: Infineon Technologies; Alternate Manufacturer: None; U/M: EA; ChType: N; VdsMax_V: 100; Value1: 0.012 ohm; Rdson45_ohm: 0.2; Value2: 69 nC; QgTyp_nC: 58; Vgs_V: 20; IdsMax_A: 69; SizeAreaWB_mm2: 79.3; SizeArea_mm2: 45.9; SizeX_mm: 10.2; SizeY_mm: 4.5; SizeZ_mm: 19.4; AEC Category: Q101
R28 R31 = ERJ-8ENF4753V: RES, 475 k, 1%, 0.25 W, 1206; Manufacturer: Panasonic; CompType: Resistor; Value: 475k; Res_ohm: 475000; Tolerance_%: 1; Power_W: 0.25; Value2: 0.25W; VDC_V: 200; TempCo: 100 ppm/C; SizeArea_mm2: 5.12; SizeX_mm: 3.2; SizeY_mm: 1.6; SizeZ_mm: 1.35; EIA_Code: E96; U/M: EA; AEC Category: Q200
R29 = CRCW06033R30JNEA: RES, 3.3, 5%, 0.1 W, 0603; Manufacturer: Vishay-Dale; CompType: Resistor; Value: 3.3; Value_Code: 3R30; Tolerance_%: 5; Power_W: 0.1; Value2: 0.1W; VDC_V: 75; TempCo: 200 ppm/C; EIA_Code: E24; U/M: EA
R30 R36 R44 R49 = RC0603FR-0710RL: RES, 10.0, 1%, 0.1 W, 0603; Manufacturer: Yageo America; CompType: Resistor; Value: 10.0; Res_ohm: 10; Value_Code: 10R0; Tolerance_%: 1; Power_W: 0.1; Value2: 0.1W; VDC_V: 150; TempCo: 200 ppm/C; EIA_Code: E96; U/M: EA
R32 R45 = CRCW0603100KFKEA: RES, 100k ohm, 1%, 0.1W, 0603; Manufacturer: Vishay-Dale; CompType: Resistor; Res_ohm: 100000; Tolerance_%: 1; Power_W: 0.1; VDC_V: 75; TempCo: 100 ppm/C; EIA_Code: E96; U/M: EA
R33 R46 = CRCW0603221KFKEA: RES, 221k ohm, 1%, 0.1W, 0603; Manufacturer: Vishay-Dale; CompType: Resistor; Res_ohm: 221000; Tolerance_%: 1; Power_W: 0.1; VDC_V: 75; TempCo: 100 ppm/C; EIA_Code: E96; U/M: EA
R34 = CRCW060310R0JNEA: RES, 10, 5%, 0.1 W, 0603; Manufacturer: Vishay-Dale; CompType: Resistor; Value: 10; Value_Code: 10R0; Tolerance_%: 5; Power_W: 0.1; Value2: 0.1W; VDC_V: 75; TempCo: 200 ppm/C; EIA_Code: E24; U/M: EA
R35 = CRCW06031R00FKEA: RES, 1.00, 1%, 0.1 W, 0603; Manufacturer: Vishay-Dale; CompType: Resistor; Value: 1.00; Res_ohm: 1; Value_Code: 1R00; Power_W: 0.1; Value2: 0.1W; VDC_V: 75; TempCo: 100 ppm/C; EIA_Code: E96; U/M: EA
R37 = CRCW12060000Z0EA: RES, 0, 5%, 0.25 W, 1206; Manufacturer: Vishay-Dale; CompType: Resistor; Value: 0; Value_Code: 0000; Tolerance_%: 5; Power_W: 0.25; Value2: 0.25W; VDC_V: 200; TempCo: 200 ppm/C; EIA_Code: E24; U/M: EA
R38 R50 R58 R63 R67 R69 R70 = CRCW060310K0FKEA: RES, 10.0k ohm, 1%, 0.1W, 0603; Manufacturer: Vishay-Dale; CompType: Resistor; Res_ohm: 10000; Value_Code: 10k0; Tolerance_%: 1; Power_W: 0.1; VDC_V: 75; TempCo: 100 ppm/C; EIA_Code: E96; U/M: EA
R39-R41 = CRA2512-FZ-R080ELF: RES, 0.08, 1%, 3 W, 2512; Manufacturer: Bourns; CompType: Resistor; Value: 0.08; Value_Code: R080; Tolerance_%: 1; Power_W: 3; Value2: 3W; VDC_V: 0; TempCo: 75 ppm/C; SizeArea_mm2: 20.16; SizeX_mm: 6.3; SizeY_mm: 3.2; SizeZ_mm: 0.71; U/M: EA; AEC Category: Q200
R42 = RC0603FR-0718K2L: RES, 18.2 k, 1%, 0.1 W, 0603; Manufacturer: Yageo America; CompType: Resistor; Value: 18.2k; Res_ohm: 18200; Value_Code: 18k2; Tolerance_%: 1; Power_W: 0.1; Value2: 0.1W; VDC_V: 150; TempCo: 200 ppm/C; SizeArea_mm2: 1.28; SizeX_mm: 1.6; SizeY_mm: 0.8; EIA_Code: E96; U/M: EA; AEC Category: Q200; Green_Lifecycle: Active; Green_REACh: Passed
R43 = RC0603FR-071ML: RES, 1.00 M, 1%, 0.1 W, 0603; Manufacturer: Yageo America; CompType: Resistor; Value: 1.00Meg; Res_ohm: 1000000; Value_Code: 1M00; Tolerance_%: 1; Power_W: 0.1; Value2: 0.1W; VDC_V: 150; TempCo: 200 ppm/C; SizeArea_mm2: 1.28; SizeX_mm: 1.6; SizeY_mm: 0.8; EIA_Code: E96; U/M: EA; AEC Category: Q200; Green_Lifecycle: Active; Green_REACh: Passed
R47 R56 = RC1206FR-0710RL: RES, 10.0, 1%, 0.25 W, 1206; Manufacturer: Yageo America; CompType: Resistor; Value: 10.0; Res_ohm: 10; Value_Code: 10R0; Tolerance_%: 1; Power_W: 0.25; Value2: 0.25W; VDC_V: 200; TempCo: 200 ppm/C; SizeArea_mm2: 5.12; SizeX_mm: 3.2; SizeY_mm: 1.6; SizeZ_mm: 1.35; EIA_Code: E96; U/M: EA; AEC Category: Q200; Green_Lifecycle: Active; Green_REACh: Passed
R48 = CRCW08052R20JNEA: RES, 2.2, 5%, 0.125 W, 0805; Manufacturer: Vishay-Dale; CompType: Resistor; Value: 2.2; Value_Code: 2R20; Tolerance_%: 5; Power_W: 0.125; Value2: 0.125W; VDC_V: 150; TempCo: 200 ppm/C; EIA_Code: E24; U/M: EA
R51 = ERJ-6RQF1R0V: RES, 1.00 ohm, 1%, 0.125W, 0805; Manufacturer: Panasonic; CompType: Resistor; Res_ohm: 1; Value_Code: 1R00; Power_W: 0.125; TempCo: 200 ppm/C; EIA_Code: E96; U/M: EA
R52 R62 = ERJ-1TYJ100U: DNP; Manufacturer: Panasonic; CompType: Resistor; Value: 10; Value_Code: 10R0; Tolerance_%: 5; Value1: 5%; Power_W: 1; Value2: 1W; VDC_V: 200; TempCo: 200 ppm/C; SizeArea_mm2: 20.16; SizeX_mm: 6.3; SizeY_mm: 3.2; SizeZ_mm: 0.71; EIA_Code: E24; U/M: EA; AEC Category: Q200
R53 R55 = CRCW060351R1FKEA: RES, 51.1, 1%, 0.1 W, 0603; Manufacturer: Vishay-Dale; CompType: Resistor; Value: 51.1; Value_Code: 51R1; Tolerance_%: 1; Power_W: 0.1; Value2: 0.1W; VDC_V: 75; TempCo: 100 ppm/C; EIA_Code: E96; U/M: EA
R54 R57 = CRCW06030000Z0EA: RES, 0, 5%, 0.1 W, 0603; Manufacturer: Vishay-Dale; CompType: Resistor; Value: 0; Value_Code: 0000; Tolerance_%: 5; Power_W: 0.1; Value2: 0.1W; VDC_V: 75; TempCo: 200 ppm/C; EIA_Code: E24; U/M: EA
R59-R61 = ERJ-1TRQF1R0U: RES, 1.00, 1%, 1 W, 2512; Manufacturer: Panasonic; CompType: Resistor; Value: 1.00; Res_ohm: 1; Value_Code: 1R00; Value2: 1W; TempCo: 100 ppm/C; SizeArea_mm2: 20.16; SizeX_mm: 6.3; SizeY_mm: 3.2; SizeZ_mm: 0.71; EIA_Code: E96; U/M: EA; AEC Category: Q200
R64 = RC0603FR-0749R9L: RES, 49.9, 1%, 0.1 W, 0603; Manufacturer: Yageo America; CompType: Resistor; Value: 49.9; Value_Code: 49R9; Tolerance_%: 1; Power_W: 0.1; Value2: 0.1W; VDC_V: 150; TempCo: 200 ppm/C; SizeArea_mm2: 1.28; SizeX_mm: 1.6; SizeY_mm: 0.8; EIA_Code: E96; U/M: EA; AEC Category: Q200
R65 = CRCW06030000Z0EA: RES, 0, 5%, 0.1 W, 0603; Manufacturer: Vishay-Dale; CompType: Resistor; Value: 0; Value_Code: 0000; Tolerance_%: 5; Power_W: 0.1; Value2: 0.1W; VDC_V: 75; TempCo: 200 ppm/C; EIA_Code: E24; U/M: EA; AEC Category: Q200
R66 = RC0603FR-071K21L: RES, 1.21 k, 1%, 0.1 W, 0603; Manufacturer: Yageo America; CompType: Resistor; Value: 1.21k; Res_ohm: 1210; Value_Code: 1k21; Tolerance_%: 1; Power_W: 0.1; Value2: 0.1W; VDC_V: 150; TempCo: 200 ppm/C; SizeArea_mm2: 1.28; SizeX_mm: 1.6; SizeY_mm: 0.8; EIA_Code: E96; U/M: EA; AEC Category: Q200
R68 = RC0603FR-07107KL: RES, 107 k, 1%, 0.1 W, 0603; Manufacturer: Yageo America; CompType: Resistor; Value: 107k; Res_ohm: 107000; Tolerance_%: 1; Power_W: 0.1; Value2: 0.1W; VDC_V: 150; TempCo: 200 ppm/C; SizeArea_mm2: 1.28; SizeX_mm: 1.6; SizeY_mm: 0.8; EIA_Code: E96; U/M: EA; AEC Category: Q200
RT1 = B57237S229M: Thermistor NTC, 22 ohm, 20%, 15x7mm; Manufacturer: TDK; Tolerance_%: 20; Power_W: 3.1; TaMin_C: -55; TaMax_C: 170; U/M: EA
RV1 = B72214S0271K101: Varistor, 430V, 4.5KA, TH; Manufacturer: TDK; SymbolCreator: a0412235
T1 = 750316599: Transformer, 280 uH, TH; Manufacturer: Wurth Elektronik; SymbolCreator: Altium; Value: 280uH; Lp: 280; DCR_ohm: 0.07; Ns1toNp: 0.152; Rs1: 0.005; SizeAreaWB_mm2: 3264; SizeArea_mm2: 3038; SizeX_mm: 62; SizeY_mm: 49; SizeZ_mm: 20
TP5 = 5010: Test Point, Multipurpose, Red, TH; Manufacturer: Keystone; CompType: Test Point Loop; U/M: EA
TP6 = 5011: Test Point, Multipurpose, Black, TH; Manufacturer: Keystone; CompType: Test Point Loop; U/M: EA
U4 U6 = UCC24610DR: GREEN Rectifier Controller Device, D0008A; Manufacturer: Texas Instruments; SymbolCreator: x0208325; CompType: IC; U/M: EA
U5 = UCC27532DBVR: 2.5-A and 5-A, 35-VMAX VDD FET and IGBT Single-Gate Driver, DBV0006A; Alternate PartNumber: UCC27532DBVT; Manufacturer: Texas Instruments; SymbolCreator: a0411947; CompType: IC; U/M: EA
U7 = UCC27714DR: High-Speed,4A, 600V High-side Low-side Gate Driver Device, D0014A (SOIC-14); Manufacturer: Texas Instruments; SymbolCreator: a0411947; SizeArea_mm2: 51.9; SizeAreaWB_mm2: 85.2; SizeX_mm: 6; SizeY_mm: 8.65; SizeZ_mm: 1.75; CompType: IC; U/M: EA
U8 = LTV-817: Opto-Isolator, 1 Channel, TH; Manufacturer: Sharp Electronics; CompType: OPTOCOUPLER; U/M: EA
U9 = TL431AIDBZR: Adjustable Precision Shunt Regulator, 34 ppm / degC, 100 mA, -40 to 85 degC, 3-pin SOT-23 (DBZ), Green (RoHS & no Sb/Br); Alternate Manufacturer: None; Alternate PartNumber: Equivalent; Manufacturer: Texas Instruments; Initial Accuracy @ 25/deg C(%): 1; Iout/Iz(Max)(mA): 100; Min Iz for Regulation(uA): 600; Rating: Catalog; SubFamily: Shunt Voltage Reference; Temp Coeff(Max)(ppm/ degree C): 92; Temp Coeff(Typ)(ppm/ degree C): 34; VO Adj(Max)(V): 36; VO Adj(Min)(V): 2.495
